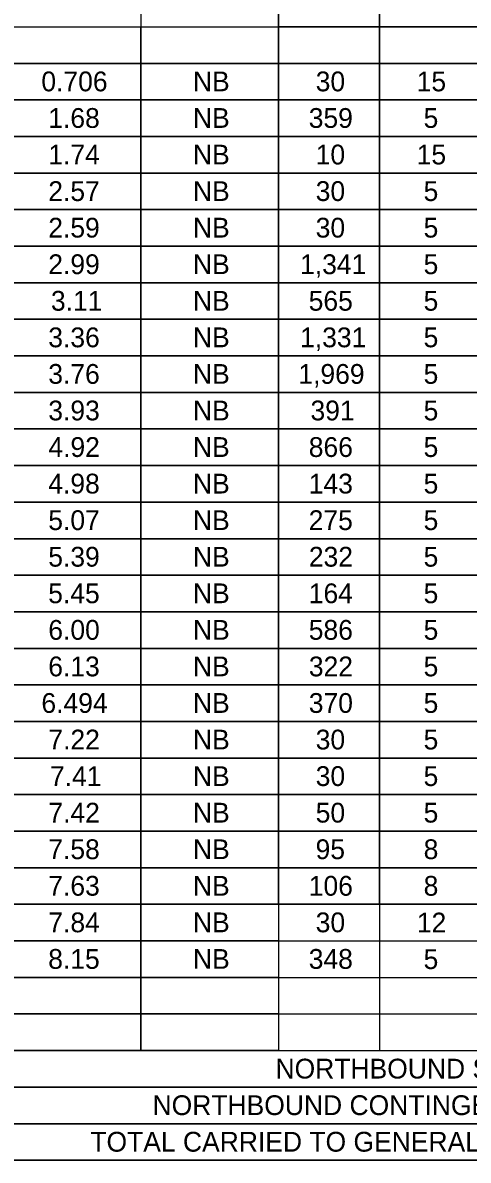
# Model space of a CAD drawing. Extents: x 0 to 34, y 0 to 22.
# Drawn here: x 7.57 to 10.67, y 5.87 to 13.81 of the extents above; entities that cross this region are included whole.
import ezdxf

# ---------------------------------------------------------------- set-up
doc = ezdxf.new("R2010")
doc.units = 0
doc.layers.add('SH_Text', color=7, linetype='Continuous')

msp = doc.modelspace()

# ---------------------------------------------------------------- linework, layer by layer
at = {"layer": 'SH_Text'}
for p, q in [((9.3497, 16.5685), (9.3497, 6.6385)), ((8.3897, 16.0735), (8.3897, 6.6385)), ((10.0547, 16.0735), (10.0547, 6.6385)), ((5.2547, 13.7785), (27.9497, 13.7785)), ((5.2547, 13.5235), (27.9497, 13.5235)), ((5.2547, 13.2685), (27.9497, 13.2685)), ((5.2547, 13.0135), (27.9497, 13.0135)), ((5.2547, 12.7585), (27.9497, 12.7585)), ((5.2547, 12.5035), (27.9497, 12.5035)), ((5.2547, 12.2485), (27.9497, 12.2485)), ((5.2547, 11.9935), (27.9497, 11.9935)), ((5.2547, 11.7385), (27.9497, 11.7385)), ((5.2547, 11.4835), (27.9497, 11.4835)), ((5.2547, 11.2285), (27.9497, 11.2285)), ((5.2547, 10.9735), (27.9497, 10.9735)), ((5.2547, 10.7185), (27.9497, 10.7185)), ((5.2547, 10.4635), (27.9497, 10.4635)), ((5.2547, 10.2085), (27.9497, 10.2085)), ((5.2547, 9.9535), (27.9497, 9.9535)), ((5.2547, 9.6985), (27.9497, 9.6985)), ((5.2547, 9.4435), (27.9497, 9.4435)), ((5.2547, 9.1885), (27.9497, 9.1885)), ((5.2547, 8.9335), (27.9497, 8.9335)), ((5.2547, 8.6785), (27.9497, 8.6785)), ((5.2547, 8.4235), (27.9497, 8.4235)), ((5.2547, 8.1685), (27.9497, 8.1685)), ((5.2547, 7.9135), (27.9497, 7.9135)), ((5.2547, 7.6585), (27.9497, 7.6585)), ((5.2547, 7.4035), (27.9497, 7.4035)), ((5.2547, 7.1485), (27.9497, 7.1485)), ((5.2547, 6.8935), (27.9497, 6.8935)), ((5.2547, 6.6385), (27.9497, 6.6385)), ((5.2547, 6.3835), (27.9497, 6.3835)), ((5.2547, 6.1285), (27.9497, 6.1285)), ((5.2547, 5.8735), (27.9497, 5.8735))]:
    msp.add_line(p, q, dxfattribs=at)
for points in [[(9.3497, 14.0335), (10.0547, 14.0335), (10.0547, 13.7785), (9.3497, 13.7785)], [(10.0547, 14.0335), (10.7597, 14.0335), (10.7597, 13.7785), (10.0547, 13.7785)], [(7.4297, 13.7785), (8.3897, 13.7785), (8.3897, 13.5235), (7.4297, 13.5235)], [(8.3897, 13.7785), (9.3497, 13.7785), (9.3497, 13.5235), (8.3897, 13.5235)], [(9.3497, 13.7785), (10.0547, 13.7785), (10.0547, 13.5235), (9.3497, 13.5235)], [(10.0547, 13.7785), (10.7597, 13.7785), (10.7597, 13.5235), (10.0547, 13.5235)], [(7.4297, 13.5235), (8.3897, 13.5235), (8.3897, 13.2685), (7.4297, 13.2685)], [(8.3897, 13.5235), (9.3497, 13.5235), (9.3497, 13.2685), (8.3897, 13.2685)], [(9.3497, 13.5235), (10.0547, 13.5235), (10.0547, 13.2685), (9.3497, 13.2685)], [(10.0547, 13.5235), (10.7597, 13.5235), (10.7597, 13.2685), (10.0547, 13.2685)], [(7.4297, 13.2685), (8.3897, 13.2685), (8.3897, 13.0135), (7.4297, 13.0135)], [(8.3897, 13.2685), (9.3497, 13.2685), (9.3497, 13.0135), (8.3897, 13.0135)], [(9.3497, 13.2685), (10.0547, 13.2685), (10.0547, 13.0135), (9.3497, 13.0135)], [(10.0547, 13.2685), (10.7597, 13.2685), (10.7597, 13.0135), (10.0547, 13.0135)], [(7.4297, 13.0135), (8.3897, 13.0135), (8.3897, 12.7585), (7.4297, 12.7585)], [(8.3897, 13.0135), (9.3497, 13.0135), (9.3497, 12.7585), (8.3897, 12.7585)], [(9.3497, 13.0135), (10.0547, 13.0135), (10.0547, 12.7585), (9.3497, 12.7585)], [(10.0547, 13.0135), (10.7597, 13.0135), (10.7597, 12.7585), (10.0547, 12.7585)], [(7.4297, 12.7585), (8.3897, 12.7585), (8.3897, 12.5035), (7.4297, 12.5035)], [(8.3897, 12.7585), (9.3497, 12.7585), (9.3497, 12.5035), (8.3897, 12.5035)], [(9.3497, 12.7585), (10.0547, 12.7585), (10.0547, 12.5035), (9.3497, 12.5035)], [(10.0547, 12.7585), (10.7597, 12.7585), (10.7597, 12.5035), (10.0547, 12.5035)], [(7.4297, 12.5035), (8.3897, 12.5035), (8.3897, 12.2485), (7.4297, 12.2485)], [(8.3897, 12.5035), (9.3497, 12.5035), (9.3497, 12.2485), (8.3897, 12.2485)], [(9.3497, 12.5035), (10.0547, 12.5035), (10.0547, 12.2485), (9.3497, 12.2485)], [(10.0547, 12.5035), (10.7597, 12.5035), (10.7597, 12.2485), (10.0547, 12.2485)], [(7.4297, 12.2485), (8.3897, 12.2485), (8.3897, 11.9935), (7.4297, 11.9935)], [(8.3897, 12.2485), (9.3497, 12.2485), (9.3497, 11.9935), (8.3897, 11.9935)], [(9.3497, 12.2485), (10.0547, 12.2485), (10.0547, 11.9935), (9.3497, 11.9935)], [(10.0547, 12.2485), (10.7597, 12.2485), (10.7597, 11.9935), (10.0547, 11.9935)], [(7.4297, 11.9935), (8.3897, 11.9935), (8.3897, 11.7385), (7.4297, 11.7385)], [(8.3897, 11.9935), (9.3497, 11.9935), (9.3497, 11.7385), (8.3897, 11.7385)], [(9.3497, 11.9935), (10.0547, 11.9935), (10.0547, 11.7385), (9.3497, 11.7385)], [(10.0547, 11.9935), (10.7597, 11.9935), (10.7597, 11.7385), (10.0547, 11.7385)], [(7.4297, 11.7385), (8.3897, 11.7385), (8.3897, 11.4835), (7.4297, 11.4835)], [(8.3897, 11.7385), (9.3497, 11.7385), (9.3497, 11.4835), (8.3897, 11.4835)], [(9.3497, 11.7385), (10.0547, 11.7385), (10.0547, 11.4835), (9.3497, 11.4835)], [(10.0547, 11.7385), (10.7597, 11.7385), (10.7597, 11.4835), (10.0547, 11.4835)], [(7.4297, 11.4835), (8.3897, 11.4835), (8.3897, 11.2285), (7.4297, 11.2285)], [(8.3897, 11.4835), (9.3497, 11.4835), (9.3497, 11.2285), (8.3897, 11.2285)], [(9.3497, 11.4835), (10.0547, 11.4835), (10.0547, 11.2285), (9.3497, 11.2285)], [(10.0547, 11.4835), (10.7597, 11.4835), (10.7597, 11.2285), (10.0547, 11.2285)], [(7.4297, 11.2285), (8.3897, 11.2285), (8.3897, 10.9735), (7.4297, 10.9735)], [(8.3897, 11.2285), (9.3497, 11.2285), (9.3497, 10.9735), (8.3897, 10.9735)], [(9.3497, 11.2285), (10.0547, 11.2285), (10.0547, 10.9735), (9.3497, 10.9735)], [(10.0547, 11.2285), (10.7597, 11.2285), (10.7597, 10.9735), (10.0547, 10.9735)], [(7.4297, 10.9735), (8.3897, 10.9735), (8.3897, 10.7185), (7.4297, 10.7185)], [(8.3897, 10.9735), (9.3497, 10.9735), (9.3497, 10.7185), (8.3897, 10.7185)], [(9.3497, 10.9735), (10.0547, 10.9735), (10.0547, 10.7185), (9.3497, 10.7185)], [(10.0547, 10.9735), (10.7597, 10.9735), (10.7597, 10.7185), (10.0547, 10.7185)], [(7.4297, 10.7185), (8.3897, 10.7185), (8.3897, 10.4635), (7.4297, 10.4635)], [(8.3897, 10.7185), (9.3497, 10.7185), (9.3497, 10.4635), (8.3897, 10.4635)], [(9.3497, 10.7185), (10.0547, 10.7185), (10.0547, 10.4635), (9.3497, 10.4635)], [(10.0547, 10.7185), (10.7597, 10.7185), (10.7597, 10.4635), (10.0547, 10.4635)], [(7.4297, 10.4635), (8.3897, 10.4635), (8.3897, 10.2085), (7.4297, 10.2085)], [(8.3897, 10.4635), (9.3497, 10.4635), (9.3497, 10.2085), (8.3897, 10.2085)], [(9.3497, 10.4635), (10.0547, 10.4635), (10.0547, 10.2085), (9.3497, 10.2085)], [(10.0547, 10.4635), (10.7597, 10.4635), (10.7597, 10.2085), (10.0547, 10.2085)], [(7.4297, 10.2085), (8.3897, 10.2085), (8.3897, 9.9535), (7.4297, 9.9535)], [(8.3897, 10.2085), (9.3497, 10.2085), (9.3497, 9.9535), (8.3897, 9.9535)], [(9.3497, 10.2085), (10.0547, 10.2085), (10.0547, 9.9535), (9.3497, 9.9535)], [(10.0547, 10.2085), (10.7597, 10.2085), (10.7597, 9.9535), (10.0547, 9.9535)], [(7.4297, 9.9535), (8.3897, 9.9535), (8.3897, 9.6985), (7.4297, 9.6985)], [(8.3897, 9.9535), (9.3497, 9.9535), (9.3497, 9.6985), (8.3897, 9.6985)], [(9.3497, 9.9535), (10.0547, 9.9535), (10.0547, 9.6985), (9.3497, 9.6985)], [(10.0547, 9.9535), (10.7597, 9.9535), (10.7597, 9.6985), (10.0547, 9.6985)], [(7.4297, 9.6985), (8.3897, 9.6985), (8.3897, 9.4435), (7.4297, 9.4435)], [(8.3897, 9.6985), (9.3497, 9.6985), (9.3497, 9.4435), (8.3897, 9.4435)], [(9.3497, 9.6985), (10.0547, 9.6985), (10.0547, 9.4435), (9.3497, 9.4435)], [(10.0547, 9.6985), (10.7597, 9.6985), (10.7597, 9.4435), (10.0547, 9.4435)], [(7.4297, 9.4435), (8.3897, 9.4435), (8.3897, 9.1885), (7.4297, 9.1885)], [(8.3897, 9.4435), (9.3497, 9.4435), (9.3497, 9.1885), (8.3897, 9.1885)], [(9.3497, 9.4435), (10.0547, 9.4435), (10.0547, 9.1885), (9.3497, 9.1885)], [(10.0547, 9.4435), (10.7597, 9.4435), (10.7597, 9.1885), (10.0547, 9.1885)], [(7.4297, 9.1885), (8.3897, 9.1885), (8.3897, 8.9335), (7.4297, 8.9335)], [(8.3897, 9.1885), (9.3497, 9.1885), (9.3497, 8.9335), (8.3897, 8.9335)], [(9.3497, 9.1885), (10.0547, 9.1885), (10.0547, 8.9335), (9.3497, 8.9335)], [(10.0547, 9.1885), (10.7597, 9.1885), (10.7597, 8.9335), (10.0547, 8.9335)], [(7.4297, 8.9335), (8.3897, 8.9335), (8.3897, 8.6785), (7.4297, 8.6785)], [(8.3897, 8.9335), (9.3497, 8.9335), (9.3497, 8.6785), (8.3897, 8.6785)], [(9.3497, 8.9335), (10.0547, 8.9335), (10.0547, 8.6785), (9.3497, 8.6785)], [(10.0547, 8.9335), (10.7597, 8.9335), (10.7597, 8.6785), (10.0547, 8.6785)], [(7.4297, 8.6785), (8.3897, 8.6785), (8.3897, 8.4235), (7.4297, 8.4235)], [(8.3897, 8.6785), (9.3497, 8.6785), (9.3497, 8.4235), (8.3897, 8.4235)], [(9.3497, 8.6785), (10.0547, 8.6785), (10.0547, 8.4235), (9.3497, 8.4235)], [(10.0547, 8.6785), (10.7597, 8.6785), (10.7597, 8.4235), (10.0547, 8.4235)], [(7.4297, 8.4235), (8.3897, 8.4235), (8.3897, 8.1685), (7.4297, 8.1685)], [(8.3897, 8.4235), (9.3497, 8.4235), (9.3497, 8.1685), (8.3897, 8.1685)], [(9.3497, 8.4235), (10.0547, 8.4235), (10.0547, 8.1685), (9.3497, 8.1685)], [(10.0547, 8.4235), (10.7597, 8.4235), (10.7597, 8.1685), (10.0547, 8.1685)], [(7.4297, 8.1685), (8.3897, 8.1685), (8.3897, 7.9135), (7.4297, 7.9135)], [(8.3897, 8.1685), (9.3497, 8.1685), (9.3497, 7.9135), (8.3897, 7.9135)], [(9.3497, 8.1685), (10.0547, 8.1685), (10.0547, 7.9135), (9.3497, 7.9135)], [(10.0547, 8.1685), (10.7597, 8.1685), (10.7597, 7.9135), (10.0547, 7.9135)], [(7.4297, 7.9135), (8.3897, 7.9135), (8.3897, 7.6585), (7.4297, 7.6585)], [(8.3897, 7.9135), (9.3497, 7.9135), (9.3497, 7.6585), (8.3897, 7.6585)], [(9.3497, 7.9135), (10.0547, 7.9135), (10.0547, 7.6585), (9.3497, 7.6585)], [(10.0547, 7.9135), (10.7597, 7.9135), (10.7597, 7.6585), (10.0547, 7.6585)], [(7.4297, 7.6585), (8.3897, 7.6585), (8.3897, 7.4035), (7.4297, 7.4035)], [(8.3897, 7.6585), (9.3497, 7.6585), (9.3497, 7.4035), (8.3897, 7.4035)], [(7.4297, 7.4035), (8.3897, 7.4035), (8.3897, 7.1485), (7.4297, 7.1485)], [(8.3897, 7.4035), (9.3497, 7.4035), (9.3497, 7.1485), (8.3897, 7.1485)], [(7.4297, 7.1485), (8.3897, 7.1485), (8.3897, 6.8935), (7.4297, 6.8935)], [(8.3897, 7.1485), (9.3497, 7.1485), (9.3497, 6.8935), (8.3897, 6.8935)], [(7.4297, 6.8935), (8.3897, 6.8935), (8.3897, 6.6385), (7.4297, 6.6385)], [(8.3897, 6.8935), (9.3497, 6.8935), (9.3497, 6.6385), (8.3897, 6.6385)], [(5.2547, 6.6385), (11.6147, 6.6385), (11.6147, 6.3835), (5.2547, 6.3835)], [(5.2547, 6.3835), (11.6147, 6.3835), (11.6147, 6.1285), (5.2547, 6.1285)], [(5.2547, 6.1285), (11.6147, 6.1285), (11.6147, 5.8735), (5.2547, 5.8735)]]:
    msp.add_lwpolyline(points, close=True, dxfattribs=at)

# ---------------------------------------------------------------- texts
for s, p in [('0.706', (7.6966, 13.3285)), ('NB', (8.7538, 13.3285)), ('30', (9.6099, 13.3285)), ('15', (10.3142, 13.3285)), ('1.68', (7.7448, 13.0735)), ('NB', (8.7538, 13.0735)), ('359', (9.5614, 13.0735)), ('5', (10.3625, 13.0735)), ('1.74', (7.7452, 12.8185)), ('NB', (8.7538, 12.8185)), ('10', (9.6099, 12.8185)), ('15', (10.3142, 12.8185)), ('2.57', (7.7449, 12.5635)), ('NB', (8.7538, 12.5635)), ('30', (9.6099, 12.5635)), ('5', (10.3625, 12.5635)), ('2.59', (7.7448, 12.3085)), ('NB', (8.7538, 12.3085)), ('30', (9.6099, 12.3085)), ('5', (10.3625, 12.3085)), ('2.99', (7.7448, 12.0535)), ('NB', (8.7538, 12.0535)), ('1,341', (9.5012, 12.0535)), ('5', (10.3625, 12.0535)), ('3.11', (7.7633, 11.7985)), ('NB', (8.7538, 11.7985)), ('565', (9.561, 11.7985)), ('5', (10.3625, 11.7985)), ('3.36', (7.7449, 11.5435)), ('NB', (8.7538, 11.5435)), ('1,331', (9.5012, 11.5435)), ('5', (10.3625, 11.5435)), ('3.76', (7.7449, 11.2885)), ('NB', (8.7538, 11.2885)), ('1,969', (9.489, 11.2885)), ('5', (10.3625, 11.2885)), ('3.93', (7.7449, 11.0335)), ('NB', (8.7538, 11.0335)), ('391', (9.5735, 11.0335)), ('5', (10.3625, 11.0335)), ('4.92', (7.7455, 10.7785)), ('NB', (8.7538, 10.7785)), ('866', (9.5615, 10.7785)), ('5', (10.3625, 10.7785)), ('4.98', (7.7448, 10.5235)), ('NB', (8.7538, 10.5235)), ('143', (9.5615, 10.5235)), ('5', (10.3625, 10.5235)), ('5.07', (7.7449, 10.2685)), ('NB', (8.7538, 10.2685)), ('275', (9.561, 10.2685)), ('5', (10.3625, 10.2685)), ('5.39', (7.7448, 10.0135)), ('NB', (8.7538, 10.0135)), ('232', (9.5621, 10.0135)), ('5', (10.3625, 10.0135)), ('5.45', (7.7444, 9.7585)), ('NB', (8.7538, 9.7585)), ('164', (9.5617, 9.7585)), ('5', (10.3625, 9.7585)), ('6.00', (7.7451, 9.5035)), ('NB', (8.7538, 9.5035)), ('586', (9.5615, 9.5035)), ('5', (10.3625, 9.5035)), ('6.13', (7.7449, 9.2485)), ('NB', (8.7538, 9.2485)), ('322', (9.5621, 9.2485)), ('5', (10.3625, 9.2485)), ('6.494', (7.6969, 8.9935)), ('NB', (8.7538, 8.9935)), ('370', (9.5617, 8.9935)), ('5', (10.3625, 8.9935)), ('7.22', (7.7455, 8.7385)), ('NB', (8.7538, 8.7385)), ('30', (9.6099, 8.7385)), ('5', (10.3625, 8.7385)), ('7.41', (7.7569, 8.4835)), ('NB', (8.7538, 8.4835)), ('30', (9.6099, 8.4835)), ('5', (10.3625, 8.4835)), ('7.42', (7.7455, 8.2285)), ('NB', (8.7538, 8.2285)), ('50', (9.6099, 8.2285)), ('5', (10.3625, 8.2285)), ('7.58', (7.7448, 7.9735)), ('NB', (8.7538, 7.9735)), ('95', (9.6092, 7.9735)), ('8', (10.3628, 7.9735)), ('7.63', (7.7449, 7.7185)), ('NB', (8.7538, 7.7185)), ('106', (9.5615, 7.7185)), ('8', (10.3628, 7.7185)), ('7.84', (7.7452, 7.4635)), ('NB', (8.7538, 7.4635)), ('30', (9.6099, 7.4635)), ('12', (10.3154, 7.462)), ('8.15', (7.7444, 7.2085)), ('NB', (8.7538, 7.2085)), ('348', (9.5614, 7.2085)), ('5', (10.3625, 7.207)), ('NORTHBOUND SUBTOTAL', (9.3295, 6.4435)), ('NORTHBOUND CONTINGENCY (10%)', (8.472, 6.1885)), ('TOTAL CARRIED TO GENERAL SUMMARY', (8.0382, 5.9335))]:
    msp.add_text(s, height=0.138, dxfattribs=at).set_placement(p)

doc.saveas('drawing.dxf')
